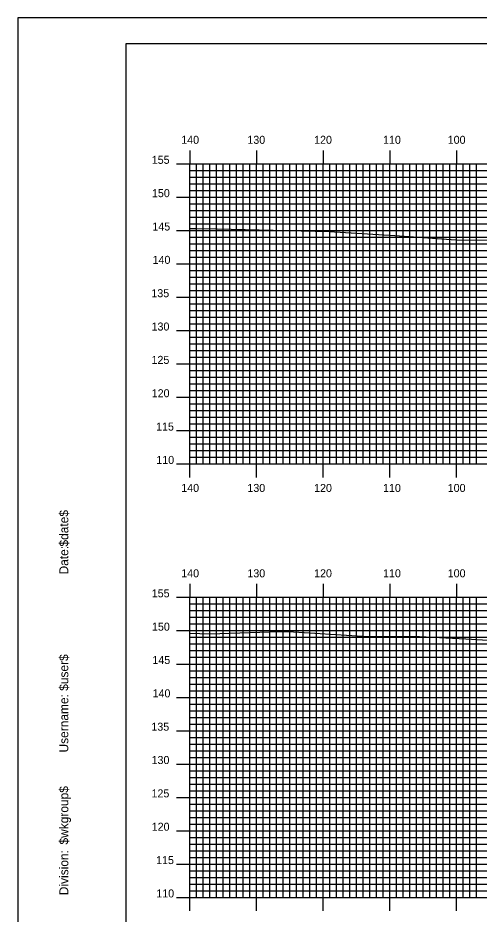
# Model space of a CAD drawing. Extents: x 1770448 to 1770792, y 442591 to 442811.
# Drawn here: x 1770448.3 to 1770517.4, y 442676.2 to 442810.5 of the extents above; entities that cross this region are included whole.
import ezdxf

# ---------------------------------------------------------------- set-up
doc = ezdxf.new("R2010")
doc.units = 0
for name, color, linetype in [('BORDER', 7, 'Continuous'), ('H_V ANNOTATION', 7, 'Continuous'), ('MAJOR', 7, 'Continuous'), ('MINOR', 7, 'Continuous'), ('PLOT BOUNDARY', 7, 'Continuous'), ('S_Roadway_Centerline', 7, 'Continuous')]:
    doc.layers.add(name, color=color, linetype=linetype)

msp = doc.modelspace()

# ---------------------------------------------------------------- linework, layer by layer
at = {"layer": 'BORDER'}
msp.add_lwpolyline([(1770464.44, 442596.67), (1770784.44, 442596.67), (1770784.44, 442806.67), (1770464.44, 442806.67)], close=True, dxfattribs=at)
at = {"layer": 'MAJOR'}
for p, q in [((1770474.04, 442790.67), (1770474.04, 442788.67)), ((1770484.04, 442790.67), (1770484.04, 442788.67)), ((1770494.04, 442790.67), (1770494.04, 442788.67)), ((1770504.04, 442790.67), (1770504.04, 442788.67)), ((1770514.04, 442790.67), (1770514.04, 442788.67)), ((1770472.04, 442788.67), (1770474.04, 442788.67)), ((1770474.04, 442788.67), (1770754.04, 442788.67)), ((1770474.04, 442743.67), (1770474.04, 442788.67)), ((1770474.04, 442743.67), (1770474.04, 442788.67)), ((1770474.04, 442788.67), (1770754.04, 442788.67)), ((1770484.04, 442743.67), (1770484.04, 442788.67)), ((1770494.04, 442743.67), (1770494.04, 442788.67)), ((1770504.04, 442743.67), (1770504.04, 442788.67)), ((1770514.04, 442743.67), (1770514.04, 442788.67)), ((1770472.04, 442783.67), (1770474.04, 442783.67)), ((1770474.04, 442783.67), (1770754.04, 442783.67)), ((1770472.04, 442778.67), (1770474.04, 442778.67)), ((1770474.04, 442778.67), (1770754.04, 442778.67)), ((1770472.04, 442773.67), (1770474.04, 442773.67)), ((1770474.04, 442773.67), (1770754.04, 442773.67)), ((1770472.04, 442768.67), (1770474.04, 442768.67)), ((1770474.04, 442768.67), (1770754.04, 442768.67)), ((1770472.04, 442763.67), (1770474.04, 442763.67)), ((1770474.04, 442763.67), (1770754.04, 442763.67)), ((1770472.04, 442758.67), (1770474.04, 442758.67)), ((1770474.04, 442758.67), (1770754.04, 442758.67)), ((1770472.04, 442753.67), (1770474.04, 442753.67)), ((1770474.04, 442753.67), (1770754.04, 442753.67)), ((1770472.04, 442748.67), (1770474.04, 442748.67)), ((1770474.04, 442748.67), (1770754.04, 442748.67)), ((1770472.04, 442743.67), (1770474.04, 442743.67)), ((1770474.04, 442743.67), (1770754.04, 442743.67)), ((1770474.04, 442743.67), (1770754.04, 442743.67)), ((1770474.04, 442741.66), (1770474.04, 442743.67)), ((1770484.04, 442741.66), (1770484.04, 442743.67)), ((1770494.04, 442741.66), (1770494.04, 442743.67)), ((1770504.04, 442741.66), (1770504.04, 442743.67)), ((1770514.04, 442741.66), (1770514.04, 442743.67)), ((1770474.04, 442725.67), (1770474.04, 442723.67)), ((1770484.04, 442725.67), (1770484.04, 442723.67)), ((1770494.04, 442725.67), (1770494.04, 442723.67)), ((1770504.04, 442725.67), (1770504.04, 442723.67)), ((1770514.04, 442725.67), (1770514.04, 442723.67)), ((1770472.04, 442723.67), (1770474.04, 442723.67)), ((1770474.04, 442723.67), (1770754.04, 442723.67)), ((1770474.04, 442678.67), (1770474.04, 442723.67)), ((1770474.04, 442678.67), (1770474.04, 442723.67)), ((1770474.04, 442723.67), (1770754.04, 442723.67)), ((1770484.04, 442678.67), (1770484.04, 442723.67)), ((1770494.04, 442678.67), (1770494.04, 442723.67)), ((1770504.04, 442678.67), (1770504.04, 442723.67)), ((1770514.04, 442678.67), (1770514.04, 442723.67)), ((1770472.04, 442718.67), (1770474.04, 442718.67)), ((1770474.04, 442718.67), (1770754.04, 442718.67)), ((1770472.04, 442713.67), (1770474.04, 442713.67)), ((1770474.04, 442713.67), (1770754.04, 442713.67)), ((1770472.04, 442708.67), (1770474.04, 442708.67)), ((1770474.04, 442708.67), (1770754.04, 442708.67)), ((1770472.04, 442703.67), (1770474.04, 442703.67)), ((1770474.04, 442703.67), (1770754.04, 442703.67)), ((1770472.04, 442698.67), (1770474.04, 442698.67)), ((1770474.04, 442698.67), (1770754.04, 442698.67)), ((1770472.04, 442693.67), (1770474.04, 442693.67)), ((1770474.04, 442693.67), (1770754.04, 442693.67)), ((1770472.04, 442688.67), (1770474.04, 442688.67)), ((1770474.04, 442688.67), (1770754.04, 442688.67)), ((1770472.04, 442683.67), (1770474.04, 442683.67)), ((1770474.04, 442683.67), (1770754.04, 442683.67)), ((1770472.04, 442678.67), (1770474.04, 442678.67)), ((1770474.04, 442678.67), (1770754.04, 442678.67)), ((1770474.04, 442678.67), (1770754.04, 442678.67)), ((1770474.04, 442676.66), (1770474.04, 442678.67)), ((1770484.04, 442676.66), (1770484.04, 442678.67)), ((1770494.04, 442676.66), (1770494.04, 442678.67)), ((1770504.04, 442676.66), (1770504.04, 442678.67)), ((1770514.04, 442676.66), (1770514.04, 442678.67))]:
    msp.add_line(p, q, dxfattribs=at)
at = {"layer": 'MINOR'}
for p, q in [((1770475.04, 442743.67), (1770475.04, 442788.67)), ((1770476.04, 442743.67), (1770476.04, 442788.67)), ((1770477.04, 442743.67), (1770477.04, 442788.67)), ((1770478.04, 442743.67), (1770478.04, 442788.67)), ((1770479.04, 442743.67), (1770479.04, 442788.67)), ((1770480.04, 442743.67), (1770480.04, 442788.67)), ((1770481.04, 442743.67), (1770481.04, 442788.67)), ((1770482.04, 442743.67), (1770482.04, 442788.67)), ((1770483.04, 442743.67), (1770483.04, 442788.67)), ((1770485.04, 442743.67), (1770485.04, 442788.67)), ((1770486.04, 442743.67), (1770486.04, 442788.67)), ((1770487.04, 442743.67), (1770487.04, 442788.67)), ((1770488.04, 442743.67), (1770488.04, 442788.67)), ((1770489.04, 442743.67), (1770489.04, 442788.67)), ((1770490.04, 442743.67), (1770490.04, 442788.67)), ((1770491.04, 442743.67), (1770491.04, 442788.67)), ((1770492.04, 442743.67), (1770492.04, 442788.67)), ((1770493.04, 442743.67), (1770493.04, 442788.67)), ((1770495.04, 442743.67), (1770495.04, 442788.67)), ((1770496.04, 442743.67), (1770496.04, 442788.67)), ((1770497.04, 442743.67), (1770497.04, 442788.67)), ((1770498.04, 442743.67), (1770498.04, 442788.67)), ((1770499.04, 442743.67), (1770499.04, 442788.67)), ((1770500.04, 442743.67), (1770500.04, 442788.67)), ((1770501.04, 442743.67), (1770501.04, 442788.67)), ((1770502.04, 442743.67), (1770502.04, 442788.67)), ((1770503.04, 442743.67), (1770503.04, 442788.67)), ((1770505.04, 442743.67), (1770505.04, 442788.67)), ((1770506.04, 442743.67), (1770506.04, 442788.67)), ((1770507.04, 442743.67), (1770507.04, 442788.67)), ((1770508.04, 442743.67), (1770508.04, 442788.67)), ((1770509.04, 442743.67), (1770509.04, 442788.67)), ((1770510.04, 442743.67), (1770510.04, 442788.67)), ((1770511.04, 442743.67), (1770511.04, 442788.67)), ((1770512.04, 442743.67), (1770512.04, 442788.67)), ((1770513.04, 442743.67), (1770513.04, 442788.67)), ((1770515.04, 442743.67), (1770515.04, 442788.67)), ((1770516.04, 442743.67), (1770516.04, 442788.67)), ((1770517.04, 442743.67), (1770517.04, 442788.67)), ((1770474.04, 442787.67), (1770754.04, 442787.67)), ((1770474.04, 442787.67), (1770476.05, 442787.67)), ((1770474.04, 442786.67), (1770754.04, 442786.67)), ((1770474.04, 442786.67), (1770476.05, 442786.67)), ((1770474.04, 442785.67), (1770754.04, 442785.67)), ((1770474.04, 442785.67), (1770476.05, 442785.67)), ((1770474.04, 442784.67), (1770754.04, 442784.67)), ((1770474.04, 442784.67), (1770476.05, 442784.67)), ((1770474.04, 442782.67), (1770754.04, 442782.67)), ((1770474.04, 442782.67), (1770476.05, 442782.67)), ((1770474.04, 442781.67), (1770754.04, 442781.67)), ((1770474.04, 442781.67), (1770476.05, 442781.67)), ((1770474.04, 442780.67), (1770754.04, 442780.67)), ((1770474.04, 442780.67), (1770476.05, 442780.67)), ((1770474.04, 442779.67), (1770754.04, 442779.67)), ((1770474.04, 442779.67), (1770476.05, 442779.67)), ((1770474.04, 442777.67), (1770754.04, 442777.67)), ((1770474.04, 442777.67), (1770476.05, 442777.67)), ((1770474.04, 442776.67), (1770754.04, 442776.67)), ((1770474.04, 442776.67), (1770476.05, 442776.67)), ((1770474.04, 442775.67), (1770754.04, 442775.67)), ((1770474.04, 442775.67), (1770476.05, 442775.67)), ((1770474.04, 442774.67), (1770754.04, 442774.67)), ((1770474.04, 442774.67), (1770476.05, 442774.67)), ((1770474.04, 442772.67), (1770754.04, 442772.67)), ((1770474.04, 442772.67), (1770476.05, 442772.67)), ((1770474.04, 442771.67), (1770754.04, 442771.67)), ((1770474.04, 442771.67), (1770476.05, 442771.67)), ((1770474.04, 442770.67), (1770754.04, 442770.67)), ((1770474.04, 442770.67), (1770476.05, 442770.67)), ((1770474.04, 442769.67), (1770754.04, 442769.67)), ((1770474.04, 442769.67), (1770476.05, 442769.67)), ((1770474.04, 442767.67), (1770754.04, 442767.67)), ((1770474.04, 442767.67), (1770476.05, 442767.67)), ((1770474.04, 442766.67), (1770754.04, 442766.67)), ((1770474.04, 442766.67), (1770476.05, 442766.67)), ((1770474.04, 442765.67), (1770754.04, 442765.67)), ((1770474.04, 442765.67), (1770476.05, 442765.67)), ((1770474.04, 442764.67), (1770754.04, 442764.67)), ((1770474.04, 442764.67), (1770476.05, 442764.67)), ((1770474.04, 442762.67), (1770754.04, 442762.67)), ((1770474.04, 442762.67), (1770476.05, 442762.67)), ((1770474.04, 442761.67), (1770754.04, 442761.67)), ((1770474.04, 442761.67), (1770476.05, 442761.67)), ((1770474.04, 442760.67), (1770754.04, 442760.67)), ((1770474.04, 442760.67), (1770476.05, 442760.67)), ((1770474.04, 442759.67), (1770754.04, 442759.67)), ((1770474.04, 442759.67), (1770476.05, 442759.67)), ((1770474.04, 442757.67), (1770754.04, 442757.67)), ((1770474.04, 442757.67), (1770476.05, 442757.67)), ((1770474.04, 442756.67), (1770754.04, 442756.67)), ((1770474.04, 442756.67), (1770476.05, 442756.67)), ((1770474.04, 442755.67), (1770754.04, 442755.67)), ((1770474.04, 442755.67), (1770476.05, 442755.67)), ((1770474.04, 442754.67), (1770754.04, 442754.67)), ((1770474.04, 442754.67), (1770476.05, 442754.67)), ((1770474.04, 442752.67), (1770754.04, 442752.67)), ((1770474.04, 442752.67), (1770476.05, 442752.67)), ((1770474.04, 442751.67), (1770754.04, 442751.67)), ((1770474.04, 442751.67), (1770476.05, 442751.67)), ((1770474.04, 442750.67), (1770754.04, 442750.67)), ((1770474.04, 442750.67), (1770476.05, 442750.67)), ((1770474.04, 442749.67), (1770754.04, 442749.67)), ((1770474.04, 442749.67), (1770476.05, 442749.67)), ((1770474.04, 442747.67), (1770754.04, 442747.67)), ((1770474.04, 442747.67), (1770476.05, 442747.67)), ((1770474.04, 442746.67), (1770754.04, 442746.67)), ((1770474.04, 442746.67), (1770476.05, 442746.67)), ((1770474.04, 442745.67), (1770754.04, 442745.67)), ((1770474.04, 442745.67), (1770476.05, 442745.67)), ((1770474.04, 442744.67), (1770754.04, 442744.67)), ((1770474.04, 442744.67), (1770476.05, 442744.67)), ((1770475.04, 442678.67), (1770475.04, 442723.67)), ((1770476.04, 442678.67), (1770476.04, 442723.67)), ((1770477.04, 442678.67), (1770477.04, 442723.67)), ((1770478.04, 442678.67), (1770478.04, 442723.67)), ((1770479.04, 442678.67), (1770479.04, 442723.67)), ((1770480.04, 442678.67), (1770480.04, 442723.67)), ((1770481.04, 442678.67), (1770481.04, 442723.67)), ((1770482.04, 442678.67), (1770482.04, 442723.67)), ((1770483.04, 442678.67), (1770483.04, 442723.67)), ((1770485.04, 442678.67), (1770485.04, 442723.67)), ((1770486.04, 442678.67), (1770486.04, 442723.67)), ((1770487.04, 442678.67), (1770487.04, 442723.67)), ((1770488.04, 442678.67), (1770488.04, 442723.67)), ((1770489.04, 442678.67), (1770489.04, 442723.67)), ((1770490.04, 442678.67), (1770490.04, 442723.67)), ((1770491.04, 442678.67), (1770491.04, 442723.67)), ((1770492.04, 442678.67), (1770492.04, 442723.67)), ((1770493.04, 442678.67), (1770493.04, 442723.67)), ((1770495.04, 442678.67), (1770495.04, 442723.67)), ((1770496.04, 442678.67), (1770496.04, 442723.67)), ((1770497.04, 442678.67), (1770497.04, 442723.67)), ((1770498.04, 442678.67), (1770498.04, 442723.67)), ((1770499.04, 442678.67), (1770499.04, 442723.67)), ((1770500.04, 442678.67), (1770500.04, 442723.67)), ((1770501.04, 442678.67), (1770501.04, 442723.67)), ((1770502.04, 442678.67), (1770502.04, 442723.67)), ((1770503.04, 442678.67), (1770503.04, 442723.67)), ((1770505.04, 442678.67), (1770505.04, 442723.67)), ((1770506.04, 442678.67), (1770506.04, 442723.67)), ((1770507.04, 442678.67), (1770507.04, 442723.67)), ((1770508.04, 442678.67), (1770508.04, 442723.67)), ((1770509.04, 442678.67), (1770509.04, 442723.67)), ((1770510.04, 442678.67), (1770510.04, 442723.67)), ((1770511.04, 442678.67), (1770511.04, 442723.67)), ((1770512.04, 442678.67), (1770512.04, 442723.67)), ((1770513.04, 442678.67), (1770513.04, 442723.67)), ((1770515.04, 442678.67), (1770515.04, 442723.67)), ((1770516.04, 442678.67), (1770516.04, 442723.67)), ((1770517.04, 442678.67), (1770517.04, 442723.67)), ((1770474.04, 442722.67), (1770754.04, 442722.67)), ((1770474.04, 442722.67), (1770476.05, 442722.67)), ((1770474.04, 442721.67), (1770754.04, 442721.67)), ((1770474.04, 442721.67), (1770476.05, 442721.67)), ((1770474.04, 442720.67), (1770754.04, 442720.67)), ((1770474.04, 442720.67), (1770476.05, 442720.67)), ((1770474.04, 442719.67), (1770754.04, 442719.67)), ((1770474.04, 442719.67), (1770476.05, 442719.67)), ((1770474.04, 442717.67), (1770754.04, 442717.67)), ((1770474.04, 442717.67), (1770476.05, 442717.67)), ((1770474.04, 442716.67), (1770754.04, 442716.67)), ((1770474.04, 442716.67), (1770476.05, 442716.67)), ((1770474.04, 442715.67), (1770754.04, 442715.67)), ((1770474.04, 442715.67), (1770476.05, 442715.67)), ((1770474.04, 442714.67), (1770754.04, 442714.67)), ((1770474.04, 442714.67), (1770476.05, 442714.67)), ((1770474.04, 442712.67), (1770754.04, 442712.67)), ((1770474.04, 442712.67), (1770476.05, 442712.67)), ((1770474.04, 442711.67), (1770754.04, 442711.67)), ((1770474.04, 442711.67), (1770476.05, 442711.67)), ((1770474.04, 442710.67), (1770754.04, 442710.67)), ((1770474.04, 442710.67), (1770476.05, 442710.67)), ((1770474.04, 442709.67), (1770754.04, 442709.67)), ((1770474.04, 442709.67), (1770476.05, 442709.67)), ((1770474.04, 442707.67), (1770754.04, 442707.67)), ((1770474.04, 442707.67), (1770476.05, 442707.67)), ((1770474.04, 442706.67), (1770754.04, 442706.67)), ((1770474.04, 442706.67), (1770476.05, 442706.67)), ((1770474.04, 442705.67), (1770754.04, 442705.67)), ((1770474.04, 442705.67), (1770476.05, 442705.67)), ((1770474.04, 442704.67), (1770754.04, 442704.67)), ((1770474.04, 442704.67), (1770476.05, 442704.67)), ((1770474.04, 442702.67), (1770754.04, 442702.67)), ((1770474.04, 442702.67), (1770476.05, 442702.67)), ((1770474.04, 442701.67), (1770754.04, 442701.67)), ((1770474.04, 442701.67), (1770476.05, 442701.67)), ((1770474.04, 442700.67), (1770754.04, 442700.67)), ((1770474.04, 442700.67), (1770476.05, 442700.67)), ((1770474.04, 442699.67), (1770754.04, 442699.67)), ((1770474.04, 442699.67), (1770476.05, 442699.67)), ((1770474.04, 442697.67), (1770754.04, 442697.67)), ((1770474.04, 442697.67), (1770476.05, 442697.67)), ((1770474.04, 442696.67), (1770754.04, 442696.67)), ((1770474.04, 442696.67), (1770476.05, 442696.67)), ((1770474.04, 442695.67), (1770754.04, 442695.67)), ((1770474.04, 442695.67), (1770476.05, 442695.67)), ((1770474.04, 442694.67), (1770754.04, 442694.67)), ((1770474.04, 442694.67), (1770476.05, 442694.67)), ((1770474.04, 442692.67), (1770754.04, 442692.67)), ((1770474.04, 442692.67), (1770476.05, 442692.67)), ((1770474.04, 442691.67), (1770754.04, 442691.67)), ((1770474.04, 442691.67), (1770476.05, 442691.67)), ((1770474.04, 442690.67), (1770754.04, 442690.67)), ((1770474.04, 442690.67), (1770476.05, 442690.67)), ((1770474.04, 442689.67), (1770754.04, 442689.67)), ((1770474.04, 442689.67), (1770476.05, 442689.67)), ((1770474.04, 442687.67), (1770754.04, 442687.67)), ((1770474.04, 442687.67), (1770476.05, 442687.67)), ((1770474.04, 442686.67), (1770754.04, 442686.67)), ((1770474.04, 442686.67), (1770476.05, 442686.67)), ((1770474.04, 442685.67), (1770754.04, 442685.67)), ((1770474.04, 442685.67), (1770476.05, 442685.67)), ((1770474.04, 442684.67), (1770754.04, 442684.67)), ((1770474.04, 442684.67), (1770476.05, 442684.67)), ((1770474.04, 442682.67), (1770754.04, 442682.67)), ((1770474.04, 442682.67), (1770476.05, 442682.67)), ((1770474.04, 442681.67), (1770754.04, 442681.67)), ((1770474.04, 442681.67), (1770476.05, 442681.67)), ((1770474.04, 442680.67), (1770754.04, 442680.67)), ((1770474.04, 442680.67), (1770476.05, 442680.67)), ((1770474.04, 442679.67), (1770754.04, 442679.67)), ((1770474.04, 442679.67), (1770476.05, 442679.67))]:
    msp.add_line(p, q, dxfattribs=at)
at = {"layer": 'PLOT BOUNDARY'}
msp.add_lwpolyline([(1770448.25, 442590.55), (1770788.25, 442590.55), (1770788.25, 442810.55), (1770448.25, 442810.55)], close=True, dxfattribs=at)
at = {"layer": 'S_Roadway_Centerline'}
for points in [[(1770474.04, 442778.99), (1770474.94, 442778.98), (1770478.16, 442778.92), (1770494.94, 442778.54), (1770504.77, 442777.9), (1770513.96, 442777.28), (1770522.24, 442777.22), (1770533.46, 442776.84), (1770534.49, 442776.79), (1770553.95, 442775.76), (1770564.01, 442775.22), (1770569.95, 442774.98), (1770574.19, 442774.71), (1770593.88, 442773.41), (1770593.89, 442773.41), (1770593.95, 442773.4), (1770612.57, 442772.47), (1770623.7, 442771.6), (1770632.95, 442771.24), (1770647.41, 442770.43)], [(1770474.04, 442718.27), (1770477.05, 442718.17), (1770487.54, 442718.53), (1770488.8, 442718.55), (1770499.92, 442717.86), (1770508.51, 442717.79), (1770515.44, 442717.43), (1770522.91, 442716.99)]]:
    msp.add_lwpolyline(points, dxfattribs=at)

# ---------------------------------------------------------------- texts
at = {"layer": 'BORDER'}
for s, p in [('$date$', (1770455.81, 442731.28)), ('Date:', (1770455.81, 442727.1)), ('$user$', (1770455.81, 442709.65)), ('Username:', (1770455.81, 442700.4)), ('$wkgroup$', (1770455.81, 442686.6)), ('Division:', (1770455.81, 442679))]:
    msp.add_text(s, height=1.339, rotation=90, dxfattribs=at).set_placement(p)
at = {"layer": 'H_V ANNOTATION'}
for s, p in [('140', (1770472.75, 442791.67)), ('130', (1770482.67, 442791.67)), ('120', (1770492.68, 442791.67)), ('110', (1770503.02, 442791.67)), ('100', (1770512.72, 442791.67)), ('155', (1770468.33, 442788.67)), ('150', (1770468.36, 442783.67)), ('145', (1770468.42, 442778.67)), ('140', (1770468.45, 442773.67)), ('135', (1770468.27, 442768.67)), ('130', (1770468.3, 442763.67)), ('125', (1770468.29, 442758.67)), ('120', (1770468.32, 442753.67)), ('115', (1770468.98, 442748.67)), ('110', (1770469.01, 442743.67)), ('140', (1770472.75, 442739.47)), ('130', (1770482.67, 442739.47)), ('120', (1770492.68, 442739.47)), ('110', (1770503.02, 442739.47)), ('100', (1770512.72, 442739.47)), ('140', (1770472.75, 442726.67)), ('130', (1770482.67, 442726.67)), ('120', (1770492.68, 442726.67)), ('110', (1770503.02, 442726.67)), ('100', (1770512.72, 442726.67)), ('155', (1770468.33, 442723.67)), ('150', (1770468.36, 442718.67)), ('145', (1770468.42, 442713.67)), ('140', (1770468.45, 442708.67)), ('135', (1770468.27, 442703.67)), ('130', (1770468.3, 442698.67)), ('125', (1770468.29, 442693.67)), ('120', (1770468.32, 442688.67)), ('115', (1770468.98, 442683.67)), ('110', (1770469.01, 442678.67))]:
    msp.add_text(s, height=1.2, dxfattribs=at).set_placement(p)
at = {"layer": 'MAJOR'}
for p in [(1770474.03, 442743.67), (1770474.03, 442678.67)]:
    msp.add_text('-', height=0.012, dxfattribs=at).set_placement(p)

doc.saveas('drawing.dxf')
